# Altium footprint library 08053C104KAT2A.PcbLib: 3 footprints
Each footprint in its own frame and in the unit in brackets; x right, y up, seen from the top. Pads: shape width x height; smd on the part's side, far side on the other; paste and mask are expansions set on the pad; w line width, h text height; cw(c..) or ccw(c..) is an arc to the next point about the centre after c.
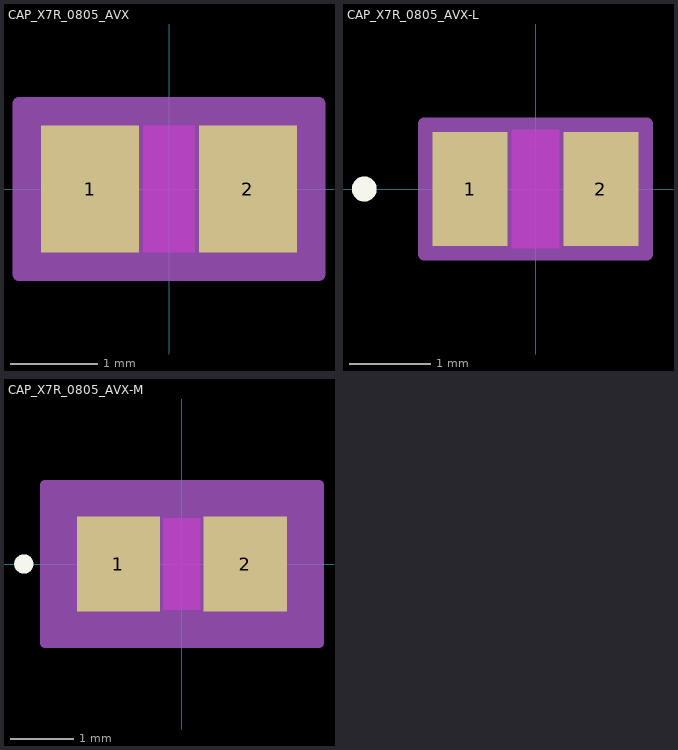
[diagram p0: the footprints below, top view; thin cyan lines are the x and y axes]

## CAP_X7R_0805_AVX [mil]
pads (2):
  rect 44x57 smd paste+0 mask+0: 1(-35.5,0) 2(35.5,0)
Top Layer keep-out:
  region: -11.5,-26.5 -11.5,26.5 11.5,26.5 11.5,-26.5
Keep-Out Layer:
  region: -11.5,-28.5 -11.5,28.5 11.5,28.5 11.5,-28.5
Mechanical 13:
  circle w0: c-30.5,0 r0
  lines w1: -43.5,-28.5 -43.5,28.5 ; -43.5,-28.5 -13.5,-28.5 -13.5,28.5 -43.5,28.5 ; -43.5,-28.5 43.5,-28.5 ; -43.5,-28.5 -43.5,28.5 ; -43.5,28.5 43.5,28.5 ; 43.5,-28.5 13.5,-28.5 13.5,28.5 43.5,28.5 ; 43.5,-28.5 43.5,28.5 ; 43.5,-28.5 43.5,28.5
Mechanical 15:
  region: 67.5,-38.5 -67.5,-38.5 -67.5,38.5 67.5,38.5
  lines w6: -67.5,-38.5 -67.5,38.5 67.5,38.5 67.5,-38.5 -67.5,-38.5
3D body "CAP_X7R_0805_AVX.step": height 37.01, standoff 0, extent -43.5,-28.5 43.5,28.5

## CAP_X7R_0805_AVX-L [mil]
pads (2):
  rect 36x55 smd paste+0 mask+0: 1(-31.5,0) 2(31.5,0)
Top Layer keep-out:
  region: -11.5,-26.5 -11.5,26.5 11.5,26.5 11.5,-26.5
Top Overlay:
  circle w6: c-82.5,0 r3
Keep-Out Layer:
  region: -11.5,-28.5 -11.5,28.5 11.5,28.5 11.5,-28.5
Mechanical 13:
  circle w0: c-26.5,0 r3
  lines w1: -43.5,-28.5 -43.5,28.5 ; -43.5,-28.5 -13.5,-28.5 -13.5,28.5 -43.5,28.5 ; -43.5,-28.5 43.5,-28.5 ; -43.5,-28.5 -43.5,28.5 ; -43.5,28.5 43.5,28.5 ; 43.5,-28.5 13.5,-28.5 13.5,28.5 43.5,28.5 ; 43.5,-28.5 43.5,28.5 ; 43.5,-28.5 43.5,28.5
Mechanical 15:
  region: 53.5,-31.5 -53.5,-31.5 -53.5,31.5 53.5,31.5
  lines w6: -53.5,-31.5 -53.5,31.5 53.5,31.5 53.5,-31.5 -53.5,-31.5
3D body "CAP_X7R_0805_AVX.step": height 37.01, standoff 0, extent -43.5,-28.5 43.5,28.5

## CAP_X7R_0805_AVX-M [mil]
pads (2):
  rect 52x59 smd paste+0 mask+0: 1(-39.5,0) 2(39.5,0)
Top Layer keep-out:
  region: -11.5,-26.5 -11.5,26.5 11.5,26.5 11.5,-26.5
Top Overlay:
  circle w6: c-98.5,0 r3
Keep-Out Layer:
  region: -11.5,-28.5 -11.5,28.5 11.5,28.5 11.5,-28.5
Mechanical 13:
  circle w0: c-34.5,0 r3
  lines w1: -43.5,-28.5 -43.5,28.5 ; -43.5,-28.5 -13.5,-28.5 -13.5,28.5 -43.5,28.5 ; -43.5,-28.5 43.5,-28.5 ; -43.5,-28.5 -43.5,28.5 ; -43.5,28.5 43.5,28.5 ; 43.5,-28.5 13.5,-28.5 13.5,28.5 43.5,28.5 ; 43.5,-28.5 43.5,28.5 ; 43.5,-28.5 43.5,28.5
Mechanical 15:
  region: 85.5,-49.5 -85.5,-49.5 -85.5,49.5 85.5,49.5
  lines w6: -85.5,-49.5 -85.5,49.5 85.5,49.5 85.5,-49.5 -85.5,-49.5
3D body "CAP_X7R_0805_AVX.step": height 37.01, standoff 0, extent -43.5,-28.5 43.5,28.5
